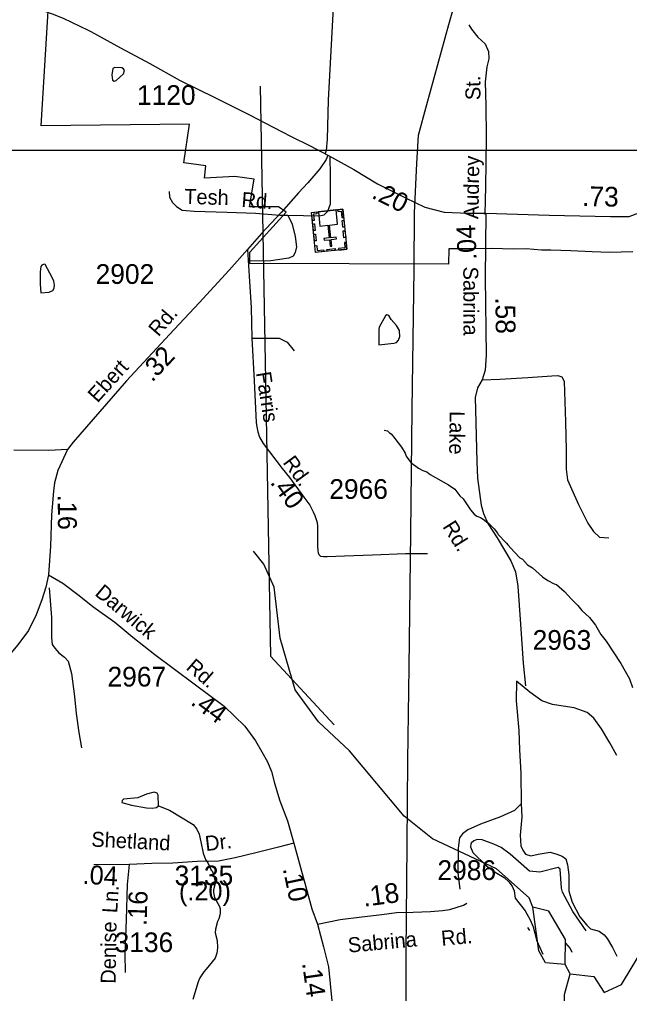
# Model space of a CAD drawing. Extents: x 1547597 to 1699558, y 810033 to 920809.
# Drawn here: x 1615688 to 1619556, y 825959 to 832135 of the extents above; entities that cross this region are included whole.
import ezdxf

# ---------------------------------------------------------------- set-up
doc = ezdxf.new("R2010")
doc.units = 0
for name, color, linetype in [('Default', 7, 'Continuous'), ('Exist Boundary Political City Limit New', 7, 'Continuous'), ('Exist Cultural Church with Cemetery CELL', 7, 'Continuous'), ('Exist Hydrographic Creek Single Shore', 7, 'Continuous'), ('Exist Hydrographic Misc Water Feature', 7, 'Continuous'), ('Exist Hydrographic Pond Under 1500 Sq Ft', 7, 'Continuous'), ('Exist Road Non-System Type 51', 7, 'Continuous'), ('Exist Road Non-System Type 51 Label', 7, 'Continuous'), ('Exist Road Secondary Mileage Hundredths English Label', 7, 'Continuous'), ('Exist Road Secondary Type 41 Attributed', 7, 'Continuous'), ('Exist Road Secondary Type 51 Attributed', 7, 'Continuous'), ('Exist Road Secondary Type 51 Label', 7, 'Continuous'), ('Exist Road Secondary Type 51 Number Label', 7, 'Continuous'), ('Exist Utilities Electrical Transmission Line', 7, 'Continuous'), ('Map Preparation Boundary City Limit Buffer Line', 7, 'Continuous'), ('Map Preparation Inset Cut Line', 7, 'Continuous')]:
    doc.layers.add(name, color=color, linetype=linetype)

msp = doc.modelspace()

# ---------------------------------------------------------------- linework, layer by layer
at = {"layer": 'Default'}
msp.add_lwpolyline([(1617215.2, 831712.6), (1617279.8, 828097.6), (1617683.2, 827661.9)], dxfattribs=at)
at = {"layer": 'Exist Boundary Political City Limit New'}
msp.add_lwpolyline([(1619576.9, 830662.1), (1619429.3, 830657.8), (1619320.1, 830662.8), (1619183.6, 830667.7), (1619058.1, 830672), (1618997.4, 830672.7), (1618950.3, 830675.8), (1618901.6, 830679.9), (1618823.7, 830677.7), (1618679.8, 830682.6), (1618558.2, 830680.2), (1618411.7, 830680.2), (1618409.3, 830583.3), (1617148.6, 830588.4), (1617148.6, 830660.3), (1617379.4, 830913.5), (1617329.8, 830947.3), (1617145.8, 830948), (1617175.9, 831123.6), (1617054.3, 831138.5), (1616860.7, 831128.5), (1616869.3, 831207.7), (1616730.8, 831226.1), (1616765.4, 831472.1), (1615825.3, 831461.5), (1615892.4, 832572.6)], dxfattribs=at)
at = {"layer": 'Exist Cultural Church with Cemetery CELL'}
for points in [[(1617764.4, 830678.3), (1617566.3, 830657.8), (1617540.1, 830911.1), (1617738.2, 830931.6)], [(1617705.3, 830928.1), (1617706.5, 830916.7), (1617728.3, 830919), (1617732.5, 830878.8), (1617743.6, 830879.9), (1617738.2, 830931.5)], [(1617573.1, 830914.5), (1617574.3, 830903.1), (1617552.4, 830900.8), (1617556.6, 830860.6), (1617545.5, 830859.5), (1617540.1, 830911.1)], [(1617695.3, 830927.1), (1617583.8, 830915.6), (1617593.1, 830825.5), (1617643.5, 830830.7), (1617651.9, 830749.7), (1617619.1, 830746.3), (1617620.3, 830735.3), (1617653.1, 830738.7), (1617657.4, 830696.7), (1617668.9, 830697.9), (1617664.6, 830739.9), (1617697.5, 830743.3), (1617696.4, 830754.2), (1617663.5, 830750.8), (1617655.1, 830831.9), (1617704.6, 830837)], [(1617558.9, 830840.4), (1617563.3, 830797.3), (1617552, 830796.1), (1617547.6, 830839.2)], [(1617745.4, 830862), (1617749.9, 830818.9), (1617738.5, 830817.8), (1617734.1, 830860.8)], [(1617565.6, 830774.8), (1617570.1, 830731.7), (1617558.8, 830730.6), (1617554.3, 830773.6)], [(1617752.3, 830795.2), (1617756.8, 830752.1), (1617745.4, 830750.9), (1617741, 830794)], [(1617561.8, 830700.9), (1617573.1, 830702.1), (1617576.4, 830670.1), (1617616.8, 830674.3), (1617617.9, 830663.2), (1617566.3, 830657.9)], [(1617759.9, 830721.4), (1617748.6, 830720.2), (1617751.9, 830688.2), (1617711.6, 830684), (1617712.7, 830673), (1617764.4, 830678.3)], [(1617690.7, 830670.7), (1617639.1, 830665.4), (1617638, 830676.7), (1617689.5, 830682)]]:
    msp.add_lwpolyline(points, close=True, dxfattribs=at)
at = {"layer": 'Exist Hydrographic Creek Single Shore'}
msp.add_line((1619179.7, 826083.8), (1619147.7, 826143.6), dxfattribs=at)
for points in [[(1618943.7, 826505.5), (1618919.7, 826565.1), (1618713.7, 826749.8), (1618307.7, 826938.6), (1618126.7, 827083.4), (1617781.7, 827497.4), (1617583.7, 827682), (1617436.7, 827885.2), (1617340.7, 828212.1), (1617303.7, 828534.6), (1617238.7, 828680.3), (1617172.7, 828763.7)], [(1619147.7, 826143.6), (1619022.8, 826152.6), (1618981.8, 826229), (1618943.7, 826505.5)], [(1619424.8, 825632.5), (1619142.7, 825776), (1619144.8, 825953.2), (1619179.7, 826083.8)]]:
    msp.add_lwpolyline(points, dxfattribs=at)
at = {"layer": 'Exist Hydrographic Misc Water Feature'}
for points in [[(1616347.8, 831790.1), (1616353.2, 831812), (1616348.8, 831822.9), (1616337.7, 831828.9), (1616293.8, 831829.8), (1616280.5, 831824.7), (1616274.1, 831783.9), (1616278.2, 831750.8), (1616289.4, 831745), (1616301.3, 831747.3), (1616347.8, 831790.1)], [(1615895.1, 830498.1), (1615851.9, 830581.2), (1615844, 830584.3), (1615830.6, 830577.5), (1615824.6, 830568.1), (1615820.3, 830534.6), (1615818.4, 830457.3), (1615822.8, 830402.4), (1615876.2, 830406.2), (1615899.6, 830415.9), (1615909.1, 830430.6), (1615910.4, 830450.9), (1615906.2, 830475.7), (1615895.1, 830498.1)], [(1618078.3, 830193.7), (1618044.8, 830232.2), (1618029.7, 830257.9), (1618018.2, 830261.7), (1618009.7, 830256.2), (1617969.9, 830185.1), (1617966, 830169.4), (1617967.4, 830072.7), (1618062.2, 830083.2), (1618079, 830087.2), (1618092.1, 830101.5), (1618099.3, 830124.2), (1618097.9, 830162.8), (1618078.3, 830193.7)], [(1618000.9, 829531.9), (1618022.8, 829527.6), (1618034.6, 829513.4), (1618044.5, 829507.3), (1618068.1, 829479), (1618111.3, 829422.4), (1618134.8, 829384.1), (1618140.5, 829366), (1618170, 829325.6), (1618217.4, 829291), (1618245.2, 829274.6), (1618271, 829266.2), (1618292.9, 829249.9), (1618407.9, 829184.3), (1618449.4, 829155.8), (1618480.9, 829115.3), (1618500.6, 829095), (1618547.7, 829026.4), (1618571.2, 828998.1), (1618589.1, 828985.8), (1618610.9, 828977.5), (1618634.7, 828963.2), (1618652.5, 828947), (1618658.5, 828944.9), (1618697.9, 828904.3), (1618719.5, 828878), (1618721.4, 828872), (1618776.6, 828815.3), (1618784.5, 828803.1), (1618827.8, 828756.6), (1618861.3, 828722.1), (1618877.2, 828713.9), (1618908.7, 828677.4), (1618940.3, 828657), (1619003.6, 828600.1), (1619039.3, 828577.7), (1619078.9, 828557.1), (1619092.9, 828552.9), (1619144.3, 828508.2), (1619187.5, 828459.6), (1619228.9, 828419.1), (1619254.5, 828386.7), (1619301.8, 828342.1), (1619341.2, 828293.5), (1619374.3, 828235.1), (1619407.7, 828192.6), (1619501.8, 828051.3), (1619556.4, 827954.6), (1619575.6, 827898.4)], [(1616570.6, 827149.2), (1616568.3, 827216), (1616560.8, 827228.8), (1616542.2, 827235.5), (1616492.7, 827223.5), (1616437.8, 827200), (1616347.2, 827191.1), (1616338.4, 827183.6), (1616338.2, 827170.4), (1616398.3, 827153.3), (1616492.9, 827135.2), (1616529.6, 827133.7), (1616557.9, 827139.1), (1616570.6, 827149.2)], [(1616570.6, 827149.2), (1616638.7, 827121.5), (1616789.4, 827031.4), (1616813, 827001.1), (1616826.6, 826968.9), (1616837.9, 826920.8), (1616852.9, 826848.6), (1616868.4, 826808.4), (1616882, 826788.2), (1616903.4, 826741.9), (1616909.3, 826735.8), (1616920.9, 826703.7), (1616926.5, 826679.6), (1616926.1, 826647.6), (1616917.7, 826615.7), (1616917.5, 826599.8), (1616925, 826567.7), (1616956.2, 826511.2), (1616960, 826495.2), (1616961.7, 826471.1), (1616959.4, 826455.2), (1616953.2, 826431.3), (1616942.9, 826415.4), (1616930.3, 826367.6), (1616930, 826343.6), (1616941.3, 826295.5), (1616944.7, 826247.4), (1616940.3, 826215.5), (1616929.8, 826183.7), (1616872.9, 826112.5), (1616856.6, 826096.7), (1616832.1, 826057.1), (1616821.8, 826033.2), (1616788.3, 825921.7)], [(1619280.5, 826355.4), (1619196.1, 826477.8), (1619132.5, 826601.1), (1619125.4, 826627), (1619117, 826747.2), (1619103.6, 826757.2), (1618986.9, 826727.9), (1618923.2, 826734.7), (1618799.4, 826842.8), (1618743.5, 826883.9), (1618697.1, 826905.2), (1618621.5, 826933.1), (1618590.8, 826935.9), (1618569.9, 826926.3), (1618551.3, 826911.8), (1618550.7, 826905.9)], [(1618550.7, 826905.9), (1618548.7, 826888.5), (1618563, 826852.8), (1618650.3, 826768.4), (1618703.8, 826728.6), (1618762.2, 826693.6), (1618791.4, 826667.5), (1618811.9, 826639.1), (1618825, 826609.5), (1618831.9, 826564.1), (1618894.7, 826482.4), (1618927.2, 826426.9), (1618946.3, 826381.3), (1618968.6, 826292.7), (1619006.2, 826208)], [(1619149.8, 826277.2), (1619179.4, 826243.2), (1619191.5, 826221)]]:
    msp.add_lwpolyline(points, dxfattribs=at)
at = {"layer": 'Exist Hydrographic Pond Under 1500 Sq Ft'}
for points in [[(1619179.7, 826083.8), (1619329.7, 826067.6), (1619395.8, 825964.6), (1619504.7, 826014.8), (1619904.7, 826676.4), (1619955.7, 826718.1), (1620055.7, 826706.2)], [(1619147.7, 826143.6), (1619149.7, 826301.1), (1619043.8, 826480.5), (1618943.7, 826505.5)]]:
    msp.add_lwpolyline(points, dxfattribs=at)
at = {"layer": 'Exist Road Non-System Type 51'}
for p, q in [((1617339.6, 830894.6), (1617390.8, 830894.8)), ((1618910.2, 826378), (1618922.1, 826358.6))]:
    msp.add_line(p, q, dxfattribs=at)
for points in [[(1617678.7, 832250), (1617646.4, 831622.9), (1617639.9, 831375.6), (1617633.5, 831304.5), (1617627, 831285.1)], [(1618537.5, 832100.2), (1618555, 832074), (1618594.2, 832023.4), (1618641.5, 831980.8), (1618662.8, 831932.4), (1618664, 831886.5), (1618651.4, 831834.7), (1618641.8, 831738.9), (1618645.6, 831588.9), (1618646.6, 831391.2), (1618646.1, 831221.3), (1618643.8, 831077.3), (1618639.5, 830898.3)], [(1617390.8, 830894.8), (1617588.6, 830889.8), (1617620.6, 830897.3), (1617643.1, 830918.9), (1617659.6, 830966.6), (1617661.1, 831057.4), (1617660.4, 831144.4), (1617657.9, 831266.4)], [(1616638.3, 831045.3), (1616640, 831009.5), (1616657.5, 830975.3), (1616683, 830949), (1616720.7, 830926.4), (1616796.4, 830919.4), (1617004.2, 830912.8), (1617184, 830906.6), (1617339.6, 830894.6)], [(1617390.8, 830894.8), (1617418.1, 830836.4), (1617436.7, 830758.2), (1617443.8, 830694), (1617437.3, 830658.1), (1617423, 830634.4), (1617396.7, 830622.7), (1617282.5, 830604.6), (1617146.8, 830602.6)], [(1617162.1, 830115.3), (1617334.2, 830114.3), (1617384.9, 830088.9), (1617430.5, 830033.2)], [(1618621.7, 829851), (1618733.7, 829855.4), (1618911.6, 829864.6), (1619063.7, 829876.3), (1619101.5, 829877.7), (1619127.4, 829869.4), (1619143, 829841.3), (1619144, 829773.2), (1619151, 829583.2), (1619154.4, 829405.2), (1619154.5, 829283.3), (1619163.3, 829215.3), (1619188.6, 829159), (1619233, 829060.4), (1619293, 828941.5), (1619328.2, 828889), (1619365.7, 828852.4), (1619425.6, 828847.6)], [(1617639.7, 828730.5), (1617749.6, 828734.7), (1617927.4, 828740.1), (1618135.3, 828748.9), (1618275.2, 828748.8)], [(1615876.5, 828530.6), (1615891.7, 828342.7), (1615891.7, 828216.9), (1615895, 828172.8), (1615912.6, 828148.6), (1615938.2, 828118.3), (1615973.6, 828091.7), (1615997.3, 828065.2), (1616018.2, 827989), (1616037.8, 827842.9), (1616048.2, 827734.8), (1616064.4, 827614.6), (1616080.8, 827516.4)], [(1618840.3, 827938.9), (1618838.4, 827814.9), (1618853.6, 827626.9), (1618859.7, 827504.9), (1618867.4, 827354.9), (1618868.5, 827160.9)], [(1619476.5, 827467.8), (1619431.7, 827548.3), (1619379, 827637), (1619330.2, 827705.7), (1619288.9, 827740.3), (1619205.4, 827769.6), (1619135.6, 827780.7), (1619067.8, 827791.6), (1619000.2, 827814.6), (1618925.1, 827869.6), (1618840.3, 827938.9)], [(1618868.5, 827160.9), (1618827.9, 827119.5), (1618737.4, 827078.9), (1618610.8, 827032.9), (1618530.2, 826996.1), (1618497.9, 826970.5), (1618477.5, 826944.9), (1618470.6, 826881), (1618468.2, 826723.2), (1618480.6, 826621.1)], [(1618868.5, 827160.9), (1618873.3, 827079), (1618863.5, 826963.1), (1618868.3, 826895.2), (1618880, 826866.9), (1618897.5, 826842.8), (1618931.3, 826832.3), (1618977.5, 826841.5), (1619053.6, 826854.4), (1619095.4, 826841.8), (1619129.1, 826829.3), (1619152.8, 826813), (1619162.2, 826774.8), (1619171.1, 826710.7), (1619172.3, 826650.7), (1619171.6, 826606.9), (1619192.7, 826538.6), (1619241.2, 826445.8), (1619286.3, 826391.2), (1619309.9, 826368.9), (1619363.6, 826354), (1619395.2, 826331.6), (1619414.9, 826307.4), (1619448, 826250.9), (1619475.1, 826196.5)]]:
    msp.add_lwpolyline(points, dxfattribs=at)
at = {"layer": 'Exist Road Secondary Type 41 Attributed'}
msp.add_lwpolyline([(1617134.8, 830676.1), (1617147.7, 830474.7), (1617157.3, 830308), (1617162.1, 830115.3), (1617176.3, 829843.5), (1617189.7, 829579.9), (1617193, 829552.1), (1617199.3, 829520.8), (1617210.4, 829487.4), (1617233, 829446.8), (1617353.9, 829287.8), (1617401.1, 829231.3), (1617490.4, 829106.9), (1617529.4, 829055.5), (1617550.8, 829013.7), (1617561.3, 828990.8), (1617567.7, 828971.3), (1617575.4, 828945.1), (1617577, 828921.9), (1617577.9, 828878.3), (1617577, 828797.1), (1617579.2, 828765.2), (1617581.5, 828753.1), (1617585.8, 828741.8), (1617596.1, 828732.6), (1617616.7, 828729), (1617639.7, 828730.5)], dxfattribs=at)
at = {"layer": 'Exist Road Secondary Type 51 Attributed'}
msp.add_line((1616383.5, 826776.9), (1616160.2, 826774.9), dxfattribs=at)
for points in [[(1615603.3, 832256), (1615701, 832238.6), (1615772.7, 832221.7), (1615870.1, 832178.5), (1615895.9, 832170.2), (1615965.4, 832143.4), (1616124.3, 832066.8), (1616140.2, 832059.2), (1616328.6, 831954.9), (1616515.1, 831856.5), (1616703.4, 831750.2), (1616931.6, 831637.3), (1617146, 831530.7), (1617354.3, 831422), (1617410.7, 831393.9), (1617531, 831334), (1617643.9, 831275.5)], [(1618645.6, 830906.2), (1619047.7, 830894.3), (1619435.7, 830886.5), (1619553.2, 830886.5), (1619721.8, 830949.2), (1619945.1, 831043.4), (1620244.6, 831137.1), (1620539.4, 831177.2), (1620754.9, 831200.7), (1620921.5, 831227.3), (1621021.4, 831271.3), (1621097.8, 831329.3), (1621552.4, 831682.3), (1621796.4, 831862), (1622008, 831980.7), (1622158.3, 832061.4)], [(1617643.9, 831275.5), (1617632.3, 831248.3), (1617592.5, 831187.8), (1617516.2, 831099.8), (1617458.4, 831035.3), (1617347.9, 830911.5), (1617222.8, 830777.2), (1617134.8, 830676.1)], [(1617643.9, 831275.5), (1617808.3, 831183.7), (1617958.8, 831093.6), (1618135.3, 831004.9), (1618258.3, 830945.2), (1618381.5, 830913.9), (1618534.4, 830906.1), (1618645.6, 830906.2)], [(1618645.6, 830906.2), (1618641.7, 830497.4), (1618648.1, 830007), (1618640.5, 829911.4), (1618621.7, 829851), (1618592.1, 829799.4), (1618578, 829738.2), (1618579, 829660.2), (1618588.2, 829329.4), (1618592.9, 829226.6), (1618616.3, 829055.5), (1618630.3, 829002), (1618658.3, 828939.6), (1618716.9, 828847.9), (1618804.8, 828702.7), (1618832.8, 828632.6), (1618848.1, 828542.2), (1618864.6, 828301.5), (1618882.5, 828053.1), (1618896.5, 827910.5)], [(1617134.8, 830676.1), (1617018.5, 830546.4), (1616828.5, 830339.1), (1616640.4, 830138.6), (1616367, 829844.6), (1616029.2, 829455.8), (1615993.8, 829408)], [(1615993.8, 829408), (1615875.1, 829402.9), (1615651.8, 829403.9)], [(1615993.8, 829408), (1615931, 829274.5), (1615910.9, 829198), (1615904.3, 829144.3), (1615890.3, 828994.5), (1615883.9, 828796.2), (1615872.1, 828613.9)], [(1615872.1, 828613.9), (1615854.5, 828536.3), (1615829.8, 828455.1), (1615794.5, 828359.8), (1615745.1, 828261), (1615678.1, 828169.2), (1615589.9, 828063.3), (1615494.7, 827904.5), (1615427.7, 827798.6), (1615367.7, 827696.2), (1615311.3, 827618.6), (1615247.8, 827540.9), (1615180.8, 827445.6), (1615022.9, 827216.6), (1614915.3, 827052.5)], [(1615872.1, 828613.9), (1615963.8, 828561), (1616066.1, 828483.3), (1616154.3, 828412.7), (1616292.3, 828314.4), (1616406.8, 828218.8), (1616547.1, 828108.7), (1616795.7, 827922.3), (1616986.4, 827781.4), (1617116.6, 827654.6), (1617184, 827561), (1617225.5, 827491.1), (1617260.4, 827427.8), (1617286.6, 827366.6), (1617306.2, 827292.4), (1617339, 827181), (1617387.2, 827054.7), (1617427.5, 826911.8)], [(1617427.5, 826911.8), (1617330.2, 826886.1), (1617186.2, 826851.2), (1617055.3, 826819.2), (1616951.1, 826798.1), (1616815.4, 826796.2), (1616661.1, 826785), (1616528.3, 826783), (1616383.5, 826776.9)], [(1617427.5, 826911.8), (1617469.7, 826758.8), (1617503.9, 826636), (1617541.7, 826494.7), (1617577.6, 826397.8)], [(1616383.5, 826776.9), (1616371.6, 826649.9), (1616363.9, 826425.2), (1616355.4, 826211.3), (1616357.4, 826092.5)], [(1617577.6, 826397.8), (1617721.4, 826428.4), (1617858.8, 826445.2), (1617985.5, 826460.7), (1618078.9, 826473.4), (1618184.5, 826474.3), (1618295.3, 826478.9), (1618371, 826485.2), (1618417, 826490.5), (1618504.6, 826518.9), (1618525.3, 826532.5)], [(1617577.6, 826397.8), (1617617, 826255.6), (1617647.1, 826128.8), (1617667.8, 825912.7), (1617681.7, 825757.3)]]:
    msp.add_lwpolyline(points, dxfattribs=at)
at = {"layer": 'Exist Utilities Electrical Transmission Line'}
msp.add_lwpolyline([(1618139.2, 825527.4), (1618139.9, 826213.2), (1618146.9, 826904.6), (1618151.3, 827436.2), (1618158.5, 828027.8), (1618170, 828879.3), (1618178.3, 829662.7), (1618190.3, 830552.2), (1618192, 830909.9), (1618206.9, 831221.4), (1618217.7, 831401.3), (1618270.7, 831596.3), (1618410.5, 832104), (1618533.4, 832537.7), (1618651.7, 832957.8), (1618836.2, 833628.6), (1619001.5, 834229.8), (1619177.1, 834856.6), (1619363.7, 835533.4), (1619467.5, 835911.7), (1619581.2, 836149.7), (1619823.2, 836665.7)], dxfattribs=at)
at = {"layer": 'Map Preparation Boundary City Limit Buffer Line'}
msp.add_lwpolyline([(1619576.9, 830662.1), (1619429.3, 830657.8), (1619320.1, 830662.8), (1619183.6, 830667.7), (1619058.1, 830672), (1618997.4, 830672.7), (1618950.3, 830675.8), (1618901.6, 830679.9), (1618823.7, 830677.7), (1618679.8, 830682.6), (1618558.2, 830680.2), (1618411.7, 830680.2), (1618409.3, 830583.3), (1617148.6, 830588.4), (1617148.6, 830660.3), (1617379.4, 830913.5), (1617329.8, 830947.3), (1617145.8, 830948), (1617175.9, 831123.6), (1617054.3, 831138.5), (1616860.7, 831128.5), (1616869.3, 831207.7), (1616730.8, 831226.1), (1616765.4, 831472.1), (1615825.3, 831461.5), (1615892.4, 832572.6)], dxfattribs=at)
at = {"layer": 'Map Preparation Inset Cut Line'}
for points in [[(1633724, 874749.3), (1571208, 874749.3), (1571208, 831307.2), (1633724, 831307.2)], [(1575502.6, 831307.2), (1641328.6, 831307.2), (1641328.6, 811336.3), (1575502.6, 811336.3)]]:
    msp.add_lwpolyline(points, close=True, dxfattribs=at)

# ---------------------------------------------------------------- texts
at = {"layer": 'Exist Road Non-System Type 51 Label'}
for s, rotation, p in [('St.', 90.2871, (1618611.4, 831623.9)), ('Audrey', 89.07606, (1618598.6, 830868.1)), ('Tesh', 358.17583, (1616731.3, 830966.6)), ('Rd.', 355.60518, (1617093.5, 830947))]:
    msp.add_text(s, height=95, rotation=rotation, dxfattribs=at).set_placement(p)
at = {"layer": 'Exist Road Secondary Mileage Hundredths English Label'}
for s, height, rotation, p in [('.20', 120, 333.3362, (1617915.4, 831006.4)), ('.73', 125, 358.84166, (1619254.6, 830952.7)), ('.04', 120, 92.28918, (1618587, 830612.7)), ('.58', 125, 270.74406, (1618705.9, 830373.1)), ('.32', 120, 46.93904, (1616529.4, 829830.9)), ('.40', 120, 306.20549, (1617273.6, 829198.6)), ('.16', 120, 270.40171, (1615930.8, 829121.2)), ('.44', 120, 323.53773, (1616767.7, 827795.1)), ('.04', 120, 357.08716, (1616086.1, 826654.4)), ('.10', 120, 281.92719, (1617357.2, 826750.2)), ('(.20)', 120, 0.25024, (1616699.4, 826548.3)), ('.18', 125, 7.72662, (1617872.7, 826508.4)), ('.16', 120, 88.04804, (1616493.8, 826386)), ('.14', 120, 278.14084, (1617479.7, 826151.1))]:
    msp.add_text(s, height=height, rotation=rotation, dxfattribs=at).set_placement(p)
at = {"layer": 'Exist Road Secondary Type 51 Label'}
for s, rotation, p in [('Sabrina', 270.24316, (1618502.1, 830568.2)), ('Rd.', 49.35704, (1616569.3, 830119.1)), ('Ebert', 47.85007, (1616182.6, 829700.2)), ('Farris', 279.06611, (1617187.6, 829894.7)), ('Lake', 269.07882, (1618417, 829652.4)), ('Rd.', 306.20534, (1617354.3, 829325.2)), ('Rd.', 302.01673, (1618367.8, 828919.4)), ('Darwick', 320.15312, (1616160.7, 828488.3)), ('Rd.', 319.16284, (1616738.7, 828018.6)), ('Shetland', 357.08708, (1616141.9, 826890.8)), ('Dr.', 6.55079, (1616870.5, 826861.8)), ('Ln.', 86.65092, (1616307.8, 826466.6)), ('Denise', 89.11949, (1616298.1, 826020.1)), ('Rd.', 5.16414, (1618366.1, 826261.3)), ('Sabrina', 5.28211, (1617775.1, 826217.6))]:
    msp.add_text(s, height=95, rotation=rotation, dxfattribs=at).set_placement(p)
at = {"layer": 'Exist Road Secondary Type 51 Number Label'}
for s, p in [('1120', (1616433, 831593.5)), ('2902', (1616170.9, 830458.5)), ('2966', (1617652.6, 829095.3)), ('2963', (1618942.1, 828138.3)), ('2967', (1616246.4, 827905.3)), ('2986', (1618338.5, 826678.6)), ('3135', (1616671.9, 826644.9)), ('3136', (1616291.5, 826221.1))]:
    msp.add_text(s, height=125, dxfattribs=at).set_placement(p)

doc.saveas('drawing.dxf')
